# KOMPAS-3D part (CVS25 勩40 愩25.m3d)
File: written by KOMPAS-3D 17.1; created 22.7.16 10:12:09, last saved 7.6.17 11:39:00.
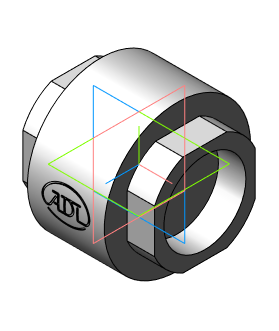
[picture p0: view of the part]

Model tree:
1. Операция без истории:2  (labels: Сталь 20  ГОСТ 1050-88)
